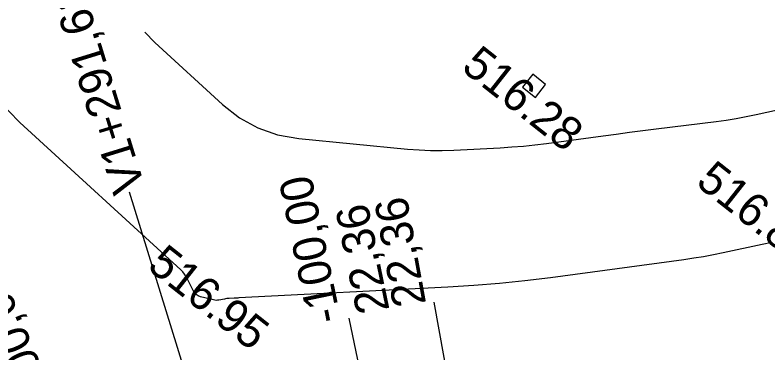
# Model space of a CAD drawing. Extents: x -636600 to -628587, y -1090963 to -1085869.
# Drawn here: x -629601.89 to -629556.21, y -1089645.96 to -1089625.48 of the extents above; entities that cross this region are included whole.
import ezdxf

# ---------------------------------------------------------------- set-up
doc = ezdxf.new("R2010")
doc.units = 0
for name, color, linetype in [('52', 7, 'Continuous'), ('Ex_Minor Contours', 7, 'Continuous'), ('koty_vše', 7, 'Continuous'), ('POLOMERY', 7, 'Continuous'), ('VRCHOLY', 7, 'Continuous')]:
    doc.layers.add(name, color=color, linetype=linetype)

msp = doc.modelspace()

# ---------------------------------------------------------------- linework, layer by layer
at = {"layer": '52'}
msp.add_lwpolyline([(-629571.099, -1089629.849), (-629570.314, -1089630.468), (-629569.695, -1089629.683), (-629570.48, -1089629.064)], close=True, dxfattribs=at)
at = {"layer": 'Ex_Minor Contours'}
for points in [[(-629594.021, -1089626.526), (-629593.414, -1089627.148), (-629589.307, -1089630.906), (-629588.276, -1089631.713), (-629587.159, -1089632.326), (-629585.956, -1089632.745), (-629584.667, -1089632.97), (-629578.075, -1089633.603), (-629577.373, -1089633.658), (-629576.671, -1089633.686), (-629575.967, -1089633.689), (-629575.264, -1089633.666), (-629572.447, -1089633.521), (-629571.744, -1089633.477), (-629571.041, -1089633.419), (-629570.341, -1089633.347), (-629569.641, -1089633.26), (-629566.21, -1089632.798), (-629565.405, -1089632.691), (-629564.6, -1089632.586), (-629563.795, -1089632.482), (-629562.989, -1089632.381), (-629559.346, -1089631.926), (-629558.737, -1089631.843), (-629558.13, -1089631.747), (-629557.525, -1089631.637), (-629556.923, -1089631.513), (-629554.52, -1089630.991)], [(-629555.971, -1089639.257), (-629556.561, -1089639.39), (-629558.925, -1089639.897), (-629559.518, -1089640.018), (-629560.112, -1089640.127), (-629560.708, -1089640.225), (-629561.306, -1089640.311), (-629569.4, -1089641.4), (-629570.95, -1089641.593), (-629572.503, -1089641.753), (-629574.059, -1089641.881), (-629575.618, -1089641.978), (-629588.305, -1089642.631), (-629588.378, -1089642.634), (-629588.452, -1089642.638), (-629588.525, -1089642.642), (-629588.599, -1089642.645), (-629588.892, -1089642.658), (-629588.966, -1089642.663), (-629589.038, -1089642.67), (-629589.111, -1089642.68), (-629589.183, -1089642.693), (-629589.525, -1089642.759), (-629589.606, -1089642.771), (-629589.686, -1089642.773), (-629589.767, -1089642.767), (-629589.847, -1089642.751), (-629590.633, -1089642.556), (-629590.78, -1089642.503), (-629590.905, -1089642.424), (-629591.007, -1089642.317), (-629591.088, -1089642.184), (-629591.415, -1089641.496), (-629591.499, -1089641.338), (-629591.598, -1089641.19), (-629591.711, -1089641.052), (-629591.837, -1089640.925), (-629601.601, -1089631.991), (-629602.942, -1089630.618)]]:
    msp.add_lwpolyline(points, dxfattribs=at)
at = {"layer": 'POLOMERY'}
for points in [[(-629574.668, -1089652.719), (-629576.449, -1089642.879)], [(-629579.58, -1089653.651), (-629581.607, -1089643.858)]]:
    msp.add_lwpolyline(points, dxfattribs=at)
at = {"layer": 'VRCHOLY'}
msp.add_lwpolyline([(-629589.034, -1089655.32), (-629594.934, -1089636.21)], dxfattribs=at)

# ---------------------------------------------------------------- texts
at = {"layer": 'koty_vše'}
for s, p in [('516.28', (-629574.881, -1089628.775)), ('516.81', (-629560.655, -1089635.746)), ('516.95', (-629593.942, -1089640.83))]:
    msp.add_text(s, height=2, rotation=321.7265, dxfattribs=at).set_placement(p)
at = {"layer": 'POLOMERY'}
for s, rotation, p in [('-100,00', 101.6937, (-629582.097, -1089643.96)), ('22,36', 100.2613, (-629576.941, -1089642.968)), ('22,36', 101.6937, (-629579.159, -1089643.352)), ('-100,00', 112.6249, (-629599.321, -1089649.079))]:
    msp.add_text(s, height=2, rotation=rotation, dxfattribs=at).set_placement(p)
at = {"layer": 'VRCHOLY'}
msp.add_text('V1+291,61', height=2, rotation=107.1593, dxfattribs=at).set_placement((-629593.979, -1089635.915))

doc.saveas('drawing.dxf')
